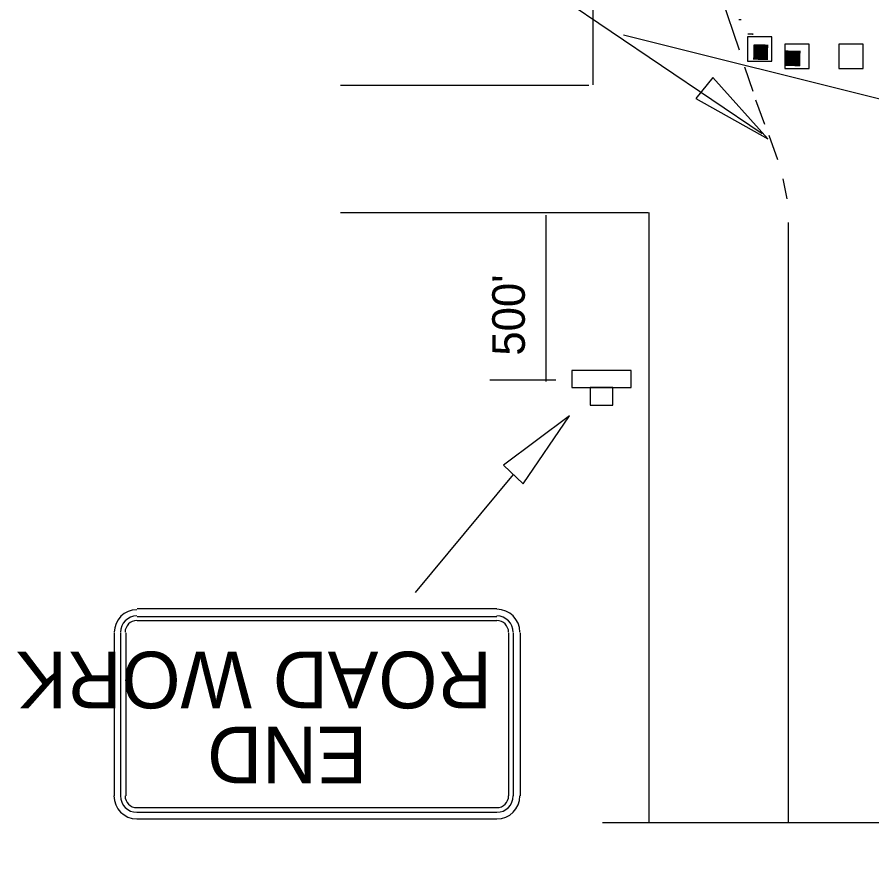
# Model space of a CAD drawing. Extents: x 1531.5 to 1538.6, y 1529.6 to 1539.6.
# Drawn here: x 1534.181 to 1535.751, y 1531.805 to 1533.359 of the extents above; entities that cross this region are included whole.
import ezdxf

# ---------------------------------------------------------------- set-up
doc = ezdxf.new("R2010")
doc.units = 0
for name, color, linetype in [('DETL-DIMS', 7, 'Continuous'), ('DETL-LINE', 7, 'Continuous'), ('DETL-NOTE', 7, 'Continuous')]:
    doc.layers.add(name, color=color, linetype=linetype)

msp = doc.modelspace()

# ---------------------------------------------------------------- linework, layer by layer
at = {"layer": 'DETL-DIMS'}
for p, q in [((1534.8358, 1533.6281), (1535.5498, 1533.1447)), ((1535.2948, 1533.3264), (1536.0759, 1533.1309)), ((1535.152, 1532.9946), (1535.152, 1532.6893)), ((1535.1704, 1532.6915), (1535.0494, 1532.6915)), ((1535.0923, 1532.5185), (1534.9123, 1532.3013))]:
    msp.add_line(p, q, dxfattribs=at)
for points in [[(1535.4592, 1533.2479), (1535.428, 1533.2089), (1535.5603, 1533.1348)], [(1535.0744, 1532.5357), (1535.1103, 1532.5011), (1535.196, 1532.6262)]]:
    msp.add_lwpolyline(points, close=True, dxfattribs=at)
at = {"layer": 'DETL-LINE'}
for p, q in [((1535.2385, 1534.1224), (1535.2385, 1533.2344)), ((1535.4244, 1533.5465), (1535.5071, 1533.2985)), ((1535.507, 1533.3541), (1535.5113, 1533.3541)), ((1535.5235, 1533.3277), (1535.5328, 1533.3277)), ((1535.5318, 1533.3275), (1535.5328, 1533.3275)), ((1535.5336, 1533.2965), (1535.5602, 1533.2965)), ((1535.5336, 1533.2963), (1535.5602, 1533.2963)), ((1535.5336, 1533.2961), (1535.5602, 1533.2961)), ((1535.5336, 1533.2959), (1535.5602, 1533.2959)), ((1535.5336, 1533.2957), (1535.5602, 1533.2957)), ((1535.5336, 1533.2955), (1535.5602, 1533.2955)), ((1535.5336, 1533.2953), (1535.5602, 1533.2953)), ((1535.5336, 1533.2951), (1535.5602, 1533.2951)), ((1535.5336, 1533.2949), (1535.5602, 1533.2949)), ((1535.5336, 1533.2946), (1535.5602, 1533.2946)), ((1535.5337, 1533.2996), (1535.5602, 1533.2996)), ((1535.5337, 1533.2995), (1535.5602, 1533.2995)), ((1535.5337, 1533.2992), (1535.5602, 1533.2992)), ((1535.5337, 1533.299), (1535.5602, 1533.299)), ((1535.5337, 1533.2988), (1535.5602, 1533.2988)), ((1535.5337, 1533.2986), (1535.5602, 1533.2986)), ((1535.5337, 1533.2984), (1535.5602, 1533.2984)), ((1535.5337, 1533.2982), (1535.5602, 1533.2982)), ((1535.5337, 1533.2979), (1535.5602, 1533.2979)), ((1535.5337, 1533.2978), (1535.5602, 1533.2978)), ((1535.5337, 1533.2975), (1535.5602, 1533.2975)), ((1535.5337, 1533.2974), (1535.5602, 1533.2974)), ((1535.5337, 1533.2971), (1535.5602, 1533.2971)), ((1535.5337, 1533.2969), (1535.5602, 1533.2969)), ((1535.5337, 1533.2967), (1535.5602, 1533.2967)), ((1535.5338, 1533.3029), (1535.5603, 1533.3029)), ((1535.5338, 1533.3028), (1535.5603, 1533.3028)), ((1535.5338, 1533.3025), (1535.5603, 1533.3025)), ((1535.5338, 1533.3023), (1535.5603, 1533.3023)), ((1535.5338, 1533.3021), (1535.5603, 1533.3021)), ((1535.5338, 1533.3019), (1535.5603, 1533.3019)), ((1535.5338, 1533.3017), (1535.5603, 1533.3017)), ((1535.5338, 1533.3015), (1535.5603, 1533.3015)), ((1535.5338, 1533.3013), (1535.5603, 1533.3013)), ((1535.5338, 1533.3011), (1535.5603, 1533.3011)), ((1535.5338, 1533.3009), (1535.5603, 1533.3009)), ((1535.5338, 1533.3007), (1535.5603, 1533.3007)), ((1535.5338, 1533.3005), (1535.5603, 1533.3005)), ((1535.5338, 1533.3003), (1535.5603, 1533.3003)), ((1535.5338, 1533.3), (1535.5602, 1533.3)), ((1535.5338, 1533.2999), (1535.5602, 1533.2999)), ((1535.5339, 1533.3063), (1535.5604, 1533.3063)), ((1535.5339, 1533.3061), (1535.5604, 1533.3061)), ((1535.5339, 1533.3059), (1535.5604, 1533.3059)), ((1535.5339, 1533.3057), (1535.5604, 1533.3057)), ((1535.5339, 1533.3054), (1535.5604, 1533.3054)), ((1535.5339, 1533.3053), (1535.5604, 1533.3053)), ((1535.5339, 1533.305), (1535.5604, 1533.305)), ((1535.5339, 1533.3049), (1535.5604, 1533.3049)), ((1535.5339, 1533.3046), (1535.5604, 1533.3046)), ((1535.5339, 1533.3044), (1535.5604, 1533.3044)), ((1535.5339, 1533.3042), (1535.5604, 1533.3042)), ((1535.5339, 1533.304), (1535.5604, 1533.304)), ((1535.5339, 1533.3038), (1535.5604, 1533.3038)), ((1535.5339, 1533.3036), (1535.5604, 1533.3036)), ((1535.5339, 1533.3033), (1535.5603, 1533.3033)), ((1535.5339, 1533.3032), (1535.5603, 1533.3032)), ((1535.534, 1533.3079), (1535.5384, 1533.3079)), ((1535.534, 1533.3077), (1535.5466, 1533.3077)), ((1535.534, 1533.3075), (1535.5548, 1533.3075)), ((1535.534, 1533.3073), (1535.5605, 1533.3073)), ((1535.534, 1533.3071), (1535.5605, 1533.3071)), ((1535.534, 1533.3069), (1535.5605, 1533.3069)), ((1535.534, 1533.3067), (1535.5604, 1533.3067)), ((1535.534, 1533.3065), (1535.5604, 1533.3065)), ((1535.5932, 1533.2965), (1535.5976, 1533.2965)), ((1535.5932, 1533.2963), (1535.6059, 1533.2963)), ((1535.5932, 1533.2961), (1535.6141, 1533.2961)), ((1535.5932, 1533.2959), (1535.6197, 1533.2959)), ((1535.5932, 1533.2956), (1535.6197, 1533.2956)), ((1535.5932, 1533.2955), (1535.6197, 1533.2955)), ((1535.5932, 1533.2952), (1535.6197, 1533.2952)), ((1535.5932, 1533.2951), (1535.6197, 1533.2951)), ((1535.5932, 1533.2948), (1535.6197, 1533.2948)), ((1535.5932, 1533.2946), (1535.6197, 1533.2946)), ((1535.5333, 1533.2833), (1535.5598, 1533.2833)), ((1535.5333, 1533.283), (1535.5598, 1533.283)), ((1535.5333, 1533.2828), (1535.5598, 1533.2828)), ((1535.5333, 1533.2826), (1535.5598, 1533.2826)), ((1535.5333, 1533.2824), (1535.5598, 1533.2824)), ((1535.5333, 1533.2822), (1535.5598, 1533.2822)), ((1535.5334, 1533.2866), (1535.5599, 1533.2866)), ((1535.5334, 1533.2863), (1535.5599, 1533.2863)), ((1535.5334, 1533.2861), (1535.5599, 1533.2861)), ((1535.5334, 1533.2859), (1535.5599, 1533.2859)), ((1535.5334, 1533.2857), (1535.5599, 1533.2857)), ((1535.5334, 1533.2855), (1535.5599, 1533.2855)), ((1535.5334, 1533.2853), (1535.5599, 1533.2853)), ((1535.5334, 1533.2851), (1535.5599, 1533.2851)), ((1535.5334, 1533.2849), (1535.5599, 1533.2849)), ((1535.5334, 1533.2847), (1535.5599, 1533.2847)), ((1535.5334, 1533.2845), (1535.5599, 1533.2845)), ((1535.5334, 1533.2842), (1535.5599, 1533.2842)), ((1535.5334, 1533.2841), (1535.5599, 1533.2841)), ((1535.5334, 1533.2838), (1535.5599, 1533.2838)), ((1535.5334, 1533.2837), (1535.5598, 1533.2837)), ((1535.5334, 1533.2834), (1535.5598, 1533.2834)), ((1535.5335, 1533.2899), (1535.56, 1533.2899)), ((1535.5335, 1533.2897), (1535.56, 1533.2897)), ((1535.5335, 1533.2895), (1535.56, 1533.2895)), ((1535.5335, 1533.2892), (1535.56, 1533.2892)), ((1535.5335, 1533.2891), (1535.56, 1533.2891)), ((1535.5335, 1533.2888), (1535.56, 1533.2888)), ((1535.5335, 1533.2887), (1535.56, 1533.2887)), ((1535.5335, 1533.2884), (1535.56, 1533.2884)), ((1535.5335, 1533.2882), (1535.56, 1533.2882)), ((1535.5335, 1533.288), (1535.56, 1533.288)), ((1535.5335, 1533.2878), (1535.56, 1533.2878)), ((1535.5335, 1533.2876), (1535.56, 1533.2876)), ((1535.5335, 1533.2874), (1535.56, 1533.2874)), ((1535.5335, 1533.2871), (1535.56, 1533.2871)), ((1535.5335, 1533.287), (1535.5599, 1533.287)), ((1535.5335, 1533.2867), (1535.5599, 1533.2867)), ((1535.5336, 1533.2945), (1535.5602, 1533.2945)), ((1535.5336, 1533.2942), (1535.5602, 1533.2942)), ((1535.5336, 1533.2941), (1535.5602, 1533.2941)), ((1535.5336, 1533.2938), (1535.5602, 1533.2938)), ((1535.5336, 1533.2936), (1535.5602, 1533.2936)), ((1535.5336, 1533.2934), (1535.5601, 1533.2934)), ((1535.5336, 1533.2932), (1535.5601, 1533.2932)), ((1535.5336, 1533.293), (1535.5601, 1533.293)), ((1535.5336, 1533.2928), (1535.5601, 1533.2928)), ((1535.5336, 1533.2925), (1535.5601, 1533.2925)), ((1535.5336, 1533.2924), (1535.5601, 1533.2924)), ((1535.5336, 1533.2921), (1535.5601, 1533.2921)), ((1535.5336, 1533.292), (1535.5601, 1533.292)), ((1535.5336, 1533.2917), (1535.5601, 1533.2917)), ((1535.5336, 1533.2915), (1535.5601, 1533.2915)), ((1535.5336, 1533.2913), (1535.5601, 1533.2913)), ((1535.5336, 1533.2911), (1535.5601, 1533.2911)), ((1535.5336, 1533.2909), (1535.5601, 1533.2909)), ((1535.5336, 1533.2907), (1535.5601, 1533.2907)), ((1535.5336, 1533.2905), (1535.5601, 1533.2905)), ((1535.5336, 1533.2903), (1535.5601, 1533.2903)), ((1535.5336, 1533.2901), (1535.56, 1533.2901)), ((1535.534, 1533.282), (1535.5598, 1533.282)), ((1535.5423, 1533.2817), (1535.5598, 1533.2817)), ((1535.5505, 1533.2816), (1535.5598, 1533.2816)), ((1535.5588, 1533.2813), (1535.5598, 1533.2813)), ((1535.5928, 1533.283), (1535.6193, 1533.283)), ((1535.5928, 1533.2827), (1535.6193, 1533.2827)), ((1535.5928, 1533.2826), (1535.6193, 1533.2826)), ((1535.5928, 1533.2823), (1535.6193, 1533.2823)), ((1535.5928, 1533.2822), (1535.6193, 1533.2822)), ((1535.5928, 1533.2819), (1535.6193, 1533.2819)), ((1535.5928, 1533.2817), (1535.6193, 1533.2817)), ((1535.5928, 1533.2815), (1535.6193, 1533.2815)), ((1535.5928, 1533.2813), (1535.6193, 1533.2813)), ((1535.5928, 1533.2811), (1535.6193, 1533.2811)), ((1535.5928, 1533.2809), (1535.6193, 1533.2809)), ((1535.5928, 1533.2807), (1535.6193, 1533.2807)), ((1535.5928, 1533.2805), (1535.6193, 1533.2805)), ((1535.5928, 1533.2803), (1535.6193, 1533.2803)), ((1535.5928, 1533.2801), (1535.6192, 1533.2801)), ((1535.5928, 1533.2798), (1535.6192, 1533.2798)), ((1535.5928, 1533.2797), (1535.6192, 1533.2797)), ((1535.5928, 1533.2794), (1535.6192, 1533.2794)), ((1535.5928, 1533.2793), (1535.6192, 1533.2793)), ((1535.5928, 1533.279), (1535.6192, 1533.279)), ((1535.5929, 1533.2863), (1535.6194, 1533.2863)), ((1535.5929, 1533.2861), (1535.6194, 1533.2861)), ((1535.5929, 1533.2859), (1535.6194, 1533.2859)), ((1535.5929, 1533.2857), (1535.6194, 1533.2857)), ((1535.5929, 1533.2855), (1535.6194, 1533.2855)), ((1535.5929, 1533.2852), (1535.6194, 1533.2852)), ((1535.5929, 1533.2851), (1535.6194, 1533.2851)), ((1535.5929, 1533.2848), (1535.6194, 1533.2848)), ((1535.5929, 1533.2847), (1535.6194, 1533.2847)), ((1535.5929, 1533.2844), (1535.6194, 1533.2844)), ((1535.5929, 1533.2842), (1535.6194, 1533.2842)), ((1535.5929, 1533.284), (1535.6194, 1533.284)), ((1535.5929, 1533.2838), (1535.6194, 1533.2838)), ((1535.5929, 1533.2836), (1535.6194, 1533.2836)), ((1535.5929, 1533.2834), (1535.6193, 1533.2834)), ((1535.5929, 1533.2831), (1535.6193, 1533.2831)), ((1535.593, 1533.2897), (1535.6195, 1533.2897)), ((1535.593, 1533.2894), (1535.6195, 1533.2894)), ((1535.593, 1533.2892), (1535.6195, 1533.2892)), ((1535.593, 1533.289), (1535.6195, 1533.289)), ((1535.593, 1533.2888), (1535.6195, 1533.2888)), ((1535.593, 1533.2886), (1535.6195, 1533.2886)), ((1535.593, 1533.2884), (1535.6195, 1533.2884)), ((1535.593, 1533.2881), (1535.6195, 1533.2881)), ((1535.593, 1533.288), (1535.6195, 1533.288)), ((1535.593, 1533.2877), (1535.6195, 1533.2877)), ((1535.593, 1533.2876), (1535.6195, 1533.2876)), ((1535.593, 1533.2873), (1535.6195, 1533.2873)), ((1535.593, 1533.2871), (1535.6195, 1533.2871)), ((1535.593, 1533.2869), (1535.6195, 1533.2869)), ((1535.593, 1533.2867), (1535.6195, 1533.2867)), ((1535.593, 1533.2865), (1535.6194, 1533.2865)), ((1535.5931, 1533.293), (1535.6196, 1533.293)), ((1535.5931, 1533.2927), (1535.6196, 1533.2927)), ((1535.5931, 1533.2925), (1535.6196, 1533.2925)), ((1535.5931, 1533.2923), (1535.6196, 1533.2923)), ((1535.5931, 1533.2921), (1535.6196, 1533.2921)), ((1535.5931, 1533.2919), (1535.6196, 1533.2919)), ((1535.5931, 1533.2917), (1535.6196, 1533.2917)), ((1535.5931, 1533.2915), (1535.6196, 1533.2915)), ((1535.5931, 1533.2913), (1535.6196, 1533.2913)), ((1535.5931, 1533.2911), (1535.6196, 1533.2911)), ((1535.5931, 1533.2909), (1535.6196, 1533.2909)), ((1535.5931, 1533.2906), (1535.6196, 1533.2906)), ((1535.5931, 1533.2905), (1535.6196, 1533.2905)), ((1535.5931, 1533.2902), (1535.6196, 1533.2902)), ((1535.5931, 1533.2901), (1535.6196, 1533.2901)), ((1535.5931, 1533.2898), (1535.6195, 1533.2898)), ((1535.5932, 1533.2944), (1535.6197, 1533.2944)), ((1535.5932, 1533.2942), (1535.6197, 1533.2942)), ((1535.5932, 1533.294), (1535.6197, 1533.294)), ((1535.5932, 1533.2938), (1535.6197, 1533.2938)), ((1535.5932, 1533.2935), (1535.6197, 1533.2935)), ((1535.5932, 1533.2934), (1535.6197, 1533.2934)), ((1535.5932, 1533.2931), (1535.6196, 1533.2931)), ((1535.5174, 1533.2675), (1535.5323, 1533.2225)), ((1535.5926, 1533.2763), (1535.6192, 1533.2763)), ((1535.5926, 1533.2761), (1535.6192, 1533.2761)), ((1535.5926, 1533.2759), (1535.6192, 1533.2759)), ((1535.5926, 1533.2757), (1535.6192, 1533.2757)), ((1535.5926, 1533.2755), (1535.6192, 1533.2755)), ((1535.5926, 1533.2753), (1535.6192, 1533.2753)), ((1535.5926, 1533.2751), (1535.6192, 1533.2751)), ((1535.5926, 1533.2749), (1535.6192, 1533.2749)), ((1535.5926, 1533.2747), (1535.6192, 1533.2747)), ((1535.5926, 1533.2744), (1535.6192, 1533.2744)), ((1535.5926, 1533.2743), (1535.6192, 1533.2743)), ((1535.5926, 1533.274), (1535.6192, 1533.274)), ((1535.5926, 1533.2739), (1535.6192, 1533.2739)), ((1535.5926, 1533.2736), (1535.6192, 1533.2736)), ((1535.5926, 1533.2734), (1535.6191, 1533.2734)), ((1535.5926, 1533.2732), (1535.6191, 1533.2732)), ((1535.5926, 1533.273), (1535.6191, 1533.273)), ((1535.5926, 1533.2728), (1535.6191, 1533.2728)), ((1535.5926, 1533.2726), (1535.6191, 1533.2726)), ((1535.5926, 1533.2723), (1535.6191, 1533.2723)), ((1535.5926, 1533.2722), (1535.6191, 1533.2722)), ((1535.5926, 1533.2719), (1535.6191, 1533.2719)), ((1535.5926, 1533.2718), (1535.6191, 1533.2718)), ((1535.5926, 1533.2715), (1535.6191, 1533.2715)), ((1535.5926, 1533.2713), (1535.6191, 1533.2713)), ((1535.5926, 1533.2711), (1535.6191, 1533.2711)), ((1535.5926, 1533.2709), (1535.6191, 1533.2709)), ((1535.5926, 1533.2707), (1535.6191, 1533.2707)), ((1535.5928, 1533.2788), (1535.6192, 1533.2788)), ((1535.5928, 1533.2786), (1535.6192, 1533.2786)), ((1535.5928, 1533.2784), (1535.6192, 1533.2784)), ((1535.5928, 1533.2782), (1535.6192, 1533.2782)), ((1535.5928, 1533.278), (1535.6192, 1533.278)), ((1535.5928, 1533.2777), (1535.6192, 1533.2777)), ((1535.5928, 1533.2776), (1535.6192, 1533.2776)), ((1535.5928, 1533.2773), (1535.6192, 1533.2773)), ((1535.5928, 1533.2772), (1535.6192, 1533.2772)), ((1535.5928, 1533.2769), (1535.6192, 1533.2769)), ((1535.5928, 1533.2768), (1535.6192, 1533.2768)), ((1535.5928, 1533.2765), (1535.6192, 1533.2765)), ((1535.5932, 1533.2705), (1535.6191, 1533.2705)), ((1535.6015, 1533.2703), (1535.6191, 1533.2703)), ((1535.6098, 1533.2701), (1535.619, 1533.2701)), ((1535.618, 1533.2699), (1535.619, 1533.2699)), ((1535.695, 1533.264), (1535.696, 1533.264)), ((1535.2315, 1533.2331), (1534.7752, 1533.2331)), ((1535.5376, 1533.2067), (1535.5538, 1533.1623)), ((1535.5618, 1533.142), (1535.578, 1533.0974)), ((1535.5877, 1533.0613), (1535.595, 1533.0246)), ((1534.7752, 1532.9995), (1535.34, 1532.9995)), ((1535.3414, 1532.9997), (1535.3414, 1532.7246)), ((1535.5973, 1532.9815), (1535.5973, 1531.8788)), ((1535.3414, 1532.7246), (1535.3414, 1531.8788)), ((1535.0625, 1532.2717), (1534.4015, 1532.2717)), ((1534.4015, 1532.2577), (1535.0625, 1532.2577)), ((1535.0625, 1532.2497), (1534.4015, 1532.2497)), ((1535.0622, 1532.25), (1535.0619, 1532.2494)), ((1534.3595, 1532.2277), (1534.3595, 1531.9277)), ((1534.3715, 1531.9277), (1534.3715, 1532.2277)), ((1534.3805, 1532.2277), (1534.3805, 1531.9277)), ((1535.0845, 1531.9277), (1535.0845, 1532.2277)), ((1535.0925, 1532.2277), (1535.0925, 1531.9277)), ((1535.1055, 1531.9277), (1535.1055, 1532.2277)), ((1535.0625, 1531.9057), (1534.4015, 1531.9057)), ((1534.4015, 1531.8977), (1534.4015, 1531.8977)), ((1534.4015, 1531.8977), (1535.0625, 1531.8977)), ((1534.4015, 1531.8857), (1535.0625, 1531.8857))]:
    msp.add_line(p, q, dxfattribs=at)
for points in [[(1535.5228, 1533.2775), (1535.5676, 1533.2775), (1535.5676, 1533.3223), (1535.5228, 1533.3223)], [(1535.5913, 1533.2643), (1535.6361, 1533.2643), (1535.6361, 1533.3091), (1535.5913, 1533.3091)], [(1535.6904, 1533.2643), (1535.7352, 1533.2643), (1535.7352, 1533.3091), (1535.6904, 1533.3091)], [(1535.3088, 1532.6784), (1535.3088, 1532.7097), (1535.1998, 1532.7097), (1535.1998, 1532.6784)], [(1535.2334, 1532.6459), (1535.2753, 1532.6459), (1535.2753, 1532.6784), (1535.2334, 1532.6784)]]:
    msp.add_lwpolyline(points, close=True, dxfattribs=at)
for points in [[(1535.5973, 1532.8315), (1535.5973, 1532.7315)], [(1535.5973, 1532.4315), (1535.5973, 1532.3315)], [(1535.5973, 1532.0315), (1535.5973, 1531.9315)], [(1535.2564, 1531.8788), (1535.9094, 1531.8788), (1535.9468, 1531.953), (1536.0029, 1531.8047), (1536.059, 1531.8788), (1536.366, 1531.8788)]]:
    msp.add_lwpolyline(points, dxfattribs=at)
for centre, radius, start, end in [((1534.401, 1532.2284), 0.0415, 90, 180), ((1534.401, 1532.2284), 0.0301, 90, 180), ((1535.0622, 1532.2284), 0.0424, 0, 90), ((1535.0622, 1532.2284), 0.0301, 0, 90), ((1534.401, 1532.2284), 0.0216, 90, 180), ((1535.0622, 1532.2284), 0.0216, 0, 90), ((1534.401, 1531.9278), 0.0421, 180, 270), ((1534.401, 1531.9278), 0.0301, 180, 270), ((1534.401, 1531.9278), 0.0216, 180, 270), ((1535.0622, 1531.9278), 0.0424, 270, 0), ((1535.0622, 1531.9278), 0.0301, 270, 0), ((1535.0622, 1531.9278), 0.0216, 270, 0)]:
    msp.add_arc(centre, radius, start, end, dxfattribs=at)

# ---------------------------------------------------------------- texts
for s, p in [('ROAD WORK', (1535.0534, 1532.1928)), ('END', (1534.8244, 1532.0548))]:
    msp.add_text(s, height=0.1041, rotation=180, dxfattribs=at).set_placement(p)
at = {"layer": 'DETL-NOTE'}
msp.add_text("500'", height=0.06, rotation=90, dxfattribs=at).set_placement((1535.1137, 1532.7367))

doc.saveas('drawing.dxf')
